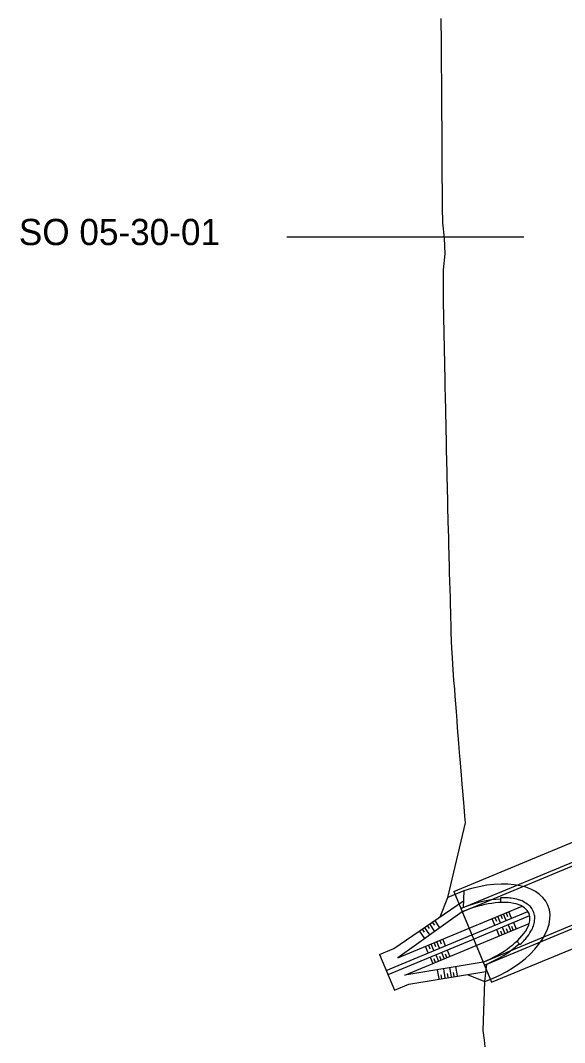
# Model space of a CAD drawing. Extents: x -723225 to -722352, y -1040354 to -1039760.
# Drawn here: x -722730.1 to -722694.9, y -1039969.1 to -1039903 of the extents above; entities that cross this region are included whole.
import ezdxf

# ---------------------------------------------------------------- set-up
doc = ezdxf.new("R2010")
doc.units = 0
for name, color, linetype in [('_PS_SO_číslo', 7, 'Continuous'), ('SO 05_25_01', 7, 'Continuous'), ('SO 05_30_01', 7, 'Continuous')]:
    doc.layers.add(name, color=color, linetype=linetype)

msp = doc.modelspace()

# ---------------------------------------------------------------- linework, layer by layer
at = {"layer": '_PS_SO_číslo'}
msp.add_line((-722712.91, -1039916.99), (-722697.57, -1039916.99), dxfattribs=at)
at = {"layer": 'SO 05_25_01'}
for p, q in [((-722702.109, -1039959.361), (-722648.727, -1039937.146)), ((-722701.648, -1039960.469), (-722648.266, -1039938.254)), ((-722701.563, -1039960.672), (-722648.182, -1039938.457)), ((-722700.208, -1039963.929), (-722646.826, -1039941.714)), ((-722700.123, -1039964.132), (-722646.742, -1039941.917)), ((-722699.662, -1039965.24), (-722646.281, -1039943.025)), ((-722703, -1039960.998), (-722702.487, -1039959.753)), ((-722701.466, -1039959.328), (-722702.487, -1039959.753)), ((-722702.109, -1039959.361), (-722699.662, -1039965.24)), ((-722701.466, -1039959.331), (-722701.507, -1039960.412)), ((-722699.092, -1039959.779), (-722699.08, -1039960.079)), ((-722705.989, -1039963.05), (-722701.49, -1039959.96)), ((-722701.648, -1039960.469), (-722700.123, -1039964.132)), ((-722701.116, -1039961.747), (-722697.689, -1039960.32)), ((-722701.563, -1039960.672), (-722705.732, -1039963.668)), ((-722700.943, -1039962.162), (-722697.312, -1039960.651)), ((-722700.828, -1039962.439), (-722697.197, -1039960.928)), ((-722699.458, -1039961.544), (-722699.631, -1039961.129)), ((-722699.446, -1039961.052), (-722699.353, -1039961.275)), ((-722699.089, -1039961.39), (-722699.261, -1039960.975)), ((-722699.077, -1039960.898), (-722698.984, -1039961.122)), ((-722698.719, -1039961.237), (-722698.892, -1039960.821)), ((-722698.73, -1039960.754), (-722698.637, -1039960.977)), ((-722698.372, -1039961.092), (-722698.545, -1039960.677)), ((-722705.732, -1039963.668), (-722701.116, -1039961.747)), ((-722704.162, -1039961.796), (-722704.025, -1039961.995)), ((-722703.658, -1039962.177), (-722703.997, -1039961.682)), ((-722703.832, -1039961.569), (-722703.695, -1039961.769)), ((-722703.333, -1039961.943), (-722703.667, -1039961.456)), ((-722703.503, -1039961.343), (-722703.366, -1039961.542)), ((-722703.008, -1039961.71), (-722703.338, -1039961.229)), ((-722700.655, -1039962.855), (-722697.228, -1039961.428)), ((-722698.973, -1039961.667), (-722698.8, -1039962.083)), ((-722698.616, -1039962.006), (-722698.709, -1039961.782)), ((-722698.604, -1039961.514), (-722698.431, -1039961.929)), ((-722698.269, -1039961.862), (-722698.362, -1039961.638)), ((-722698.257, -1039961.369), (-722698.084, -1039961.785)), ((-722706.483, -1039964.468), (-722700.943, -1039962.162)), ((-722706.368, -1039964.745), (-722700.828, -1039962.439)), ((-722703.982, -1039962.41), (-722704.327, -1039961.909)), ((-722702.657, -1039962.875), (-722702.83, -1039962.46)), ((-722699.343, -1039961.821), (-722699.17, -1039962.236)), ((-722698.985, -1039962.16), (-722699.078, -1039961.936)), ((-722706.913, -1039963.435), (-722705.989, -1039963.05)), ((-722705.271, -1039964.776), (-722700.655, -1039962.855)), ((-722703.765, -1039963.336), (-722703.938, -1039962.921)), ((-722703.753, -1039962.844), (-722703.66, -1039963.068)), ((-722703.396, -1039963.183), (-722703.568, -1039962.767)), ((-722703.384, -1039962.69), (-722703.291, -1039962.914)), ((-722703.026, -1039963.029), (-722703.199, -1039962.614)), ((-722703.015, -1039962.537), (-722702.922, -1039962.76)), ((-722697.833, -1039962.805), (-722698.036, -1039962.585)), ((-722706.913, -1039963.435), (-722705.952, -1039965.744)), ((-722703.65, -1039963.613), (-722703.477, -1039964.029)), ((-722703.292, -1039963.952), (-722703.385, -1039963.729)), ((-722703.28, -1039963.46), (-722703.107, -1039963.875)), ((-722702.923, -1039963.798), (-722703.016, -1039963.575)), ((-722702.911, -1039963.306), (-722702.738, -1039963.721)), ((-722702.553, -1039963.645), (-722702.646, -1039963.421)), ((-722702.542, -1039963.152), (-722702.369, -1039963.568)), ((-722700.208, -1039963.929), (-722705.271, -1039964.776)), ((-722703.179, -1039964.426), (-722703.076, -1039965.021)), ((-722702.784, -1039964.36), (-722702.682, -1039964.953)), ((-722702.39, -1039964.294), (-722702.288, -1039964.884)), ((-722701.995, -1039964.228), (-722701.893, -1039964.816)), ((-722700.103, -1039965.198), (-722699.982, -1039964.072)), ((-722705.028, -1039965.36), (-722700.031, -1039964.532)), ((-722702.879, -1039964.987), (-722702.92, -1039964.748)), ((-722702.485, -1039964.918), (-722702.526, -1039964.68)), ((-722702.09, -1039964.85), (-722702.132, -1039964.612)), ((-722701.237, -1039964.732), (-722700.103, -1039965.2)), ((-722705.952, -1039965.744), (-722705.028, -1039965.36))]:
    msp.add_line(p, q, dxfattribs=at)
for major_axis, ratio, start_param, end_param in [((-4.871, -2.027), 0.565617, 1.496541, 4.597404), ((-3.925, -1.633), 0.46674, 4.054487, 4.712389), ((3.644, 1.517), 0.446867, 4.712389, 7.853982), ((-3.925, -1.633), 0.46674, 1.570796, 2.228692)]:
    msp.add_ellipse((-722700.886, -1039962.301), major_axis=major_axis, ratio=ratio, start_param=start_param, end_param=end_param, dxfattribs=at)
msp.add_open_spline([(-722697.833, -1039962.805), (-722697.562, -1039962.553), (-722697.339, -1039962.293), (-722697.033, -1039961.796), (-722696.935, -1039961.559), (-722696.857, -1039961.086), (-722696.877, -1039960.849), (-722697.072, -1039960.423), (-722697.236, -1039960.251), (-722697.642, -1039959.989), (-722697.884, -1039959.899), (-722698.43, -1039959.788), (-722698.732, -1039959.768), (-722699.069, -1039959.778), (-722699.08, -1039959.779), (-722699.092, -1039959.779)], degree=3, dxfattribs=at)
at = {"layer": 'SO 05_30_01'}
for points in [[(-722702.487, -1039959.753), (-722701.359, -1039954.918), (-722701.396, -1039954.482), (-722701.451, -1039953.868), (-722701.533, -1039952.863), (-722701.569, -1039952.425), (-722701.622, -1039951.816), (-722701.701, -1039950.81), (-722701.736, -1039950.371), (-722701.787, -1039949.766), (-722701.864, -1039948.761), (-722701.897, -1039948.319), (-722701.946, -1039947.72), (-722702.021, -1039946.714), (-722702.054, -1039946.271), (-722702.101, -1039945.676), (-722702.174, -1039944.67), (-722702.206, -1039944.226), (-722702.241, -1039943.633), (-722702.271, -1039942.618), (-722702.284, -1039942.169), (-722702.304, -1039941.574), (-722702.331, -1039940.56), (-722702.357, -1039939.601), (-722702.363, -1039939.517), (-722702.389, -1039938.503), (-722702.415, -1039937.488), (-722702.426, -1039937.036), (-722702.443, -1039936.448), (-722702.467, -1039935.433), (-722702.491, -1039934.418), (-722702.502, -1039933.965), (-722702.517, -1039933.382), (-722702.54, -1039932.367), (-722702.563, -1039931.352), (-722702.573, -1039930.898), (-722702.587, -1039930.319), (-722702.608, -1039929.304), (-722702.63, -1039928.289), (-722702.651, -1039927.274), (-722702.66, -1039926.819), (-722702.673, -1039926.246), (-722702.693, -1039925.231), (-722702.714, -1039924.216), (-722702.734, -1039923.201), (-722702.754, -1039922.186), (-722702.767, -1039921.169), (-722702.771, -1039920.151), (-722702.775, -1039919.133), (-722702.662, -1039918.092), (-722702.711, -1039917.082), (-722702.83, -1039916.087), (-722702.849, -1039915.071), (-722702.852, -1039914.053), (-722702.855, -1039913.034), (-722702.861, -1039912.016), (-722702.867, -1039910.999), (-722702.872, -1039910.037), (-722702.873, -1039909.985), (-722702.879, -1039908.967), (-722702.886, -1039907.949), (-722702.892, -1039906.931), (-722702.899, -1039905.913), (-722702.901, -1039905.462), (-722702.906, -1039904.901), (-722702.915, -1039903.883), (-722702.918, -1039903.432), (-722702.926, -1039902.871)], [(-722700.074, -1039969.413), (-722700.131, -1039968.997), (-722700.222, -1039968.364), (-722700.103, -1039965.198)]]:
    msp.add_lwpolyline(points, dxfattribs=at)

# ---------------------------------------------------------------- texts
at = {"layer": '_PS_SO_číslo'}
msp.add_text('SO 05-30-01', height=1.7, dxfattribs=at).set_placement((-722730.25, -1039917.53))

doc.saveas('drawing.dxf')
